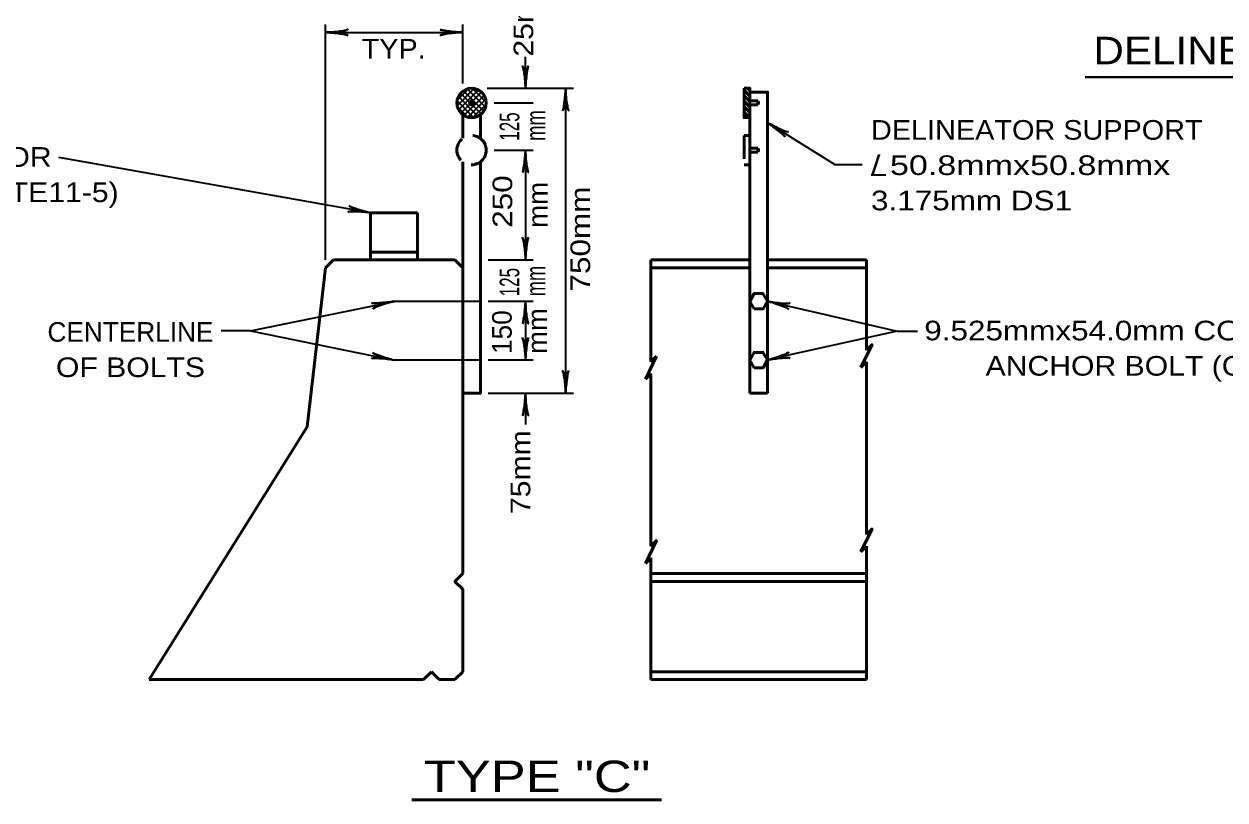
# Model space of a CAD drawing. Extents: x -105 to 751, y -65 to 479.
# Drawn here: x 308.2 to 492, y 149.8 to 268.5 of the extents above; entities that cross this region are included whole.
import ezdxf
from ezdxf.enums import TextEntityAlignment as Align

# ---------------------------------------------------------------- set-up
doc = ezdxf.new("R2010")
doc.units = 0
doc.header["$LTSCALE"] = 1.2
doc.linetypes.add('MEDIUM_DASHED', pattern=[4.5, 3, -1.5])
doc.layers.add('1', color=7, linetype='Continuous', lineweight=35)

msp = doc.modelspace()

# ---------------------------------------------------------------- hatches: boundary and pattern name
at = {"layer": '1'}
msp.add_hatch(color=256, dxfattribs=at).paths.add_polyline_path([(377.019, 256.406, 1), (376.419, 256.406, 1)])

# ---------------------------------------------------------------- linework, layer by layer
for p, q in [((354.369, 232.4), (354.369, 268.4)), ((375.369, 259.406), (375.369, 268.4)), ((354.369, 267.2), (375.369, 267.2)), ((384.969, 258.656), (384.969, 263.456)), ((374.513, 255.985), (377.138, 258.61)), ((374.514, 256.835), (376.293, 258.613)), ((377.688, 254.38), (374.695, 257.373)), ((374.733, 255.356), (377.767, 258.39)), ((378.2, 254.716), (375.031, 257.885)), ((375.088, 254.863), (378.261, 258.036)), ((378.597, 255.168), (375.484, 258.281)), ((375.558, 254.485), (378.64, 257.567)), ((378.869, 255.745), (376.06, 258.553)), ((378.962, 256.5), (376.814, 258.648)), ((379.119, 258.656), (392.319, 258.656)), ((391.119, 258.656), (391.119, 212)), ((377.037, 254.182), (374.498, 256.722)), ((376.131, 254.24), (374.553, 255.818)), ((376.155, 254.234), (378.892, 256.971)), ((376.938, 254.168), (378.953, 256.182)), ((380.169, 256.406), (386.169, 256.406)), ((380.169, 249.192), (386.169, 249.192)), ((384.969, 249.192), (384.969, 232.4)), ((361.269, 239.6), (313.525, 248.049)), ((437.882, 245.401), (440.147, 245.401)), ((379.269, 232.4), (386.169, 232.4)), ((342.873, 221.554), (364.869, 226.054)), ((378.069, 226.054), (364.869, 226.054)), ((386.169, 226.054), (379.269, 226.054)), ((384.969, 226.054), (384.969, 217.054)), ((342.873, 221.554), (338.372, 221.554)), ((342.873, 221.554), (364.869, 217.054)), ((441.854, 221.484), (444.959, 221.484)), ((378.069, 217.054), (364.869, 217.054)), ((386.169, 217.054), (379.269, 217.054)), ((379.269, 212), (392.319, 212)), ((384.969, 212), (384.969, 207.2))]:
    msp.add_line(p, q, dxfattribs=at)
at = {"layer": '1', "lineweight": 40}
msp.add_line((470.651, 260.331), (560.871, 260.331), dxfattribs=at)
at = {"layer": '1', "lineweight": 53}
for p, q in [((419.319, 257.466), (418.419, 258.366)), ((419.319, 256.618), (418.419, 257.518)), ((419.319, 258.315), (418.979, 258.656)), ((419.319, 255.769), (418.419, 256.669)), ((419.319, 254.921), (418.419, 255.821)), ((420.519, 256.706), (419.319, 256.706)), ((420.519, 256.106), (419.319, 256.106)), ((420.519, 256.706), (420.519, 256.106)), ((420.819, 256.406), (420.519, 256.406)), ((375.369, 250.993), (375.369, 254.593)), ((378.069, 250.992), (378.069, 254.592)), ((419.236, 254.156), (418.419, 254.972)), ((419.319, 254.156), (419.319, 212)), ((420.519, 249.492), (419.319, 249.492)), ((420.519, 248.892), (419.319, 248.892)), ((420.519, 249.492), (420.519, 248.892)), ((420.819, 249.192), (420.519, 249.192)), ((375.369, 247.392), (375.369, 184.4)), ((361.269, 239.6), (361.269, 232.4)), ((361.269, 239.6), (368.469, 239.6)), ((368.469, 239.6), (368.469, 232.4)), ((361.269, 233.6), (368.469, 233.6)), ((354.369, 231.2), (355.569, 232.4)), ((374.169, 232.4), (355.569, 232.4)), ((375.369, 231.2), (374.169, 232.4)), ((404.169, 216.8), (404.169, 232.4)), ((404.169, 232.4), (419.319, 232.4)), ((422.019, 232.4), (437.169, 232.4)), ((437.169, 218.6), (437.169, 232.4)), ((404.169, 231.2), (419.319, 231.2)), ((422.019, 231.2), (437.169, 231.2)), ((405.018, 217.649), (403.321, 214.152)), ((404.169, 216.8), (405.018, 217.649)), ((436.321, 215.952), (437.169, 216.8)), ((437.169, 216.8), (437.169, 190.4)), ((403.321, 214.152), (404.169, 215)), ((404.169, 215), (404.169, 188.6)), ((419.319, 212), (422.019, 212)), ((436.321, 187.752), (437.169, 188.6)), ((437.169, 188.6), (437.169, 168.2)), ((403.321, 185.952), (404.169, 186.8)), ((404.169, 186.8), (404.169, 168.2)), ((404.169, 184.4), (437.169, 184.4)), ((375.369, 182), (375.369, 169.4)), ((404.169, 183.2), (437.169, 183.2)), ((369.369, 168.2), (370.569, 169.4)), ((371.769, 168.2), (370.569, 169.4)), ((375.369, 169.4), (374.169, 168.2)), ((404.169, 169.4), (437.169, 169.4)), ((369.369, 168.2), (327.369, 168.2)), ((371.769, 168.2), (374.169, 168.2)), ((404.169, 168.2), (437.169, 168.2)), ((367.574, 149.773), (405.797, 149.773))]:
    msp.add_line(p, q, dxfattribs=at)
at = {"layer": '1', "linetype": 'MEDIUM_DASHED', "lineweight": 53}
for p, q in [((419.319, 251.442), (418.419, 251.442)), ((418.419, 251.442), (418.419, 246.942)), ((419.319, 246.942), (418.419, 246.942))]:
    msp.add_line(p, q, dxfattribs=at)
at = {"layer": '1', "lineweight": 53}
for points in [[(418.419, 258.656), (418.419, 254.156), (419.319, 254.156), (419.319, 258.656)], [(419.994, 224.892), (421.344, 224.908), (422.006, 226.085), (421.318, 227.246), (419.968, 227.231), (419.306, 226.054)], [(419.994, 215.892), (421.344, 215.908), (422.006, 217.085), (421.318, 218.246), (419.968, 218.231), (419.306, 217.054)]]:
    msp.add_lwpolyline(points, close=True, dxfattribs=at)
for points in [[(419.319, 258.056), (422.019, 258.056), (422.019, 212)], [(375.369, 212), (378.069, 212), (378.069, 247.393)], [(327.369, 168.2), (351.534, 206.871), (354.369, 231.2)], [(437.169, 218.6), (438.018, 219.449), (436.321, 215.952)], [(437.169, 190.4), (438.018, 191.249), (436.321, 187.752)], [(404.169, 188.6), (405.018, 189.449), (403.321, 185.952)], [(375.369, 182), (374.169, 183.2), (375.369, 184.4)]]:
    msp.add_lwpolyline(points, dxfattribs=at)
at = {"layer": '1'}
for points in [[(422.019, 253.397), (432.337, 246.996), (436.491, 246.996)], [(422.006, 226.085), (441.854, 221.484), (422.006, 217.085)]]:
    msp.add_lwpolyline(points, dxfattribs=at)
at = {"layer": '1', "lineweight": 53}
for radius in [2.25, 0.3]:
    msp.add_circle((376.719, 256.406), radius, dxfattribs=at)
at = {"layer": '1', "linetype": 'MEDIUM_DASHED', "lineweight": 53}
msp.add_circle((376.719, 249.192), 2.25, dxfattribs=at)
at = {"layer": '1', "lineweight": 40}
for centre, major_axis, ratio, start_param, end_param in [((355.714, 266.946), (-2.108, 0.211), 0.07063, 3.1407148, 5.41811), ((355.714, 266.946), (-2.108, 0.211), 0.07063, 3.1407148, 5.41811), ((355.679, 267.532), (-2.143, -0.187), 0.122415, 0.8963533, 3.1415927), ((355.679, 267.532), (-2.143, -0.187), 0.122415, 0.8963533, 3.1415927), ((374.06, 266.869), (2.143, 0.187), 0.122415, 0.8963533, 3.1415927), ((374.025, 267.454), (2.108, -0.211), 0.07063, 3.1407148, 5.41811), ((384.638, 259.965), (0.187, -2.143), 0.122415, 0.8963533, 3.1415927), ((384.638, 259.965), (0.187, -2.143), 0.122415, 0.8963533, 3.1415927), ((385.223, 260), (-0.211, -2.108), 0.07063, 3.1407148, 5.41811), ((385.223, 260), (-0.211, -2.108), 0.07063, 3.1407148, 5.41811), ((390.865, 257.311), (0.211, 2.108), 0.07063, 3.1407148, 5.41811), ((391.451, 257.346), (-0.187, 2.143), 0.122415, 0.8963533, 3.1415927), ((423.028, 252.472), (-1.68, 1.29), 0.07063, 3.1407148, 5.41811), ((423.028, 252.472), (-1.68, 1.29), 0.07063, 3.1407148, 5.41811), ((423.307, 252.988), (-1.92, 0.97), 0.122415, 0.8963533, 3.1415927), ((423.307, 252.988), (-1.92, 0.97), 0.122415, 0.8963533, 3.1415927), ((384.715, 247.848), (0.211, 2.108), 0.07063, 3.1407148, 5.41811), ((384.715, 247.848), (0.211, 2.108), 0.07063, 3.1407148, 5.41811), ((385.301, 247.883), (-0.187, 2.143), 0.122415, 0.8963533, 3.1415927), ((385.301, 247.883), (-0.187, 2.143), 0.122415, 0.8963533, 3.1415927), ((359.922, 239.502), (2.143, -0.189), 0.122415, 0.8963533, 3.1415927), ((359.99, 240.084), (2.039, -0.575), 0.07063, 3.1407148, 5.41811), ((384.638, 233.71), (0.187, -2.143), 0.122415, 0.8963533, 3.1415927), ((384.638, 233.71), (0.187, -2.143), 0.122415, 0.8963533, 3.1415927), ((385.223, 233.745), (-0.211, -2.108), 0.07063, 3.1407148, 5.41811), ((385.223, 233.745), (-0.211, -2.108), 0.07063, 3.1407148, 5.41811), ((363.501, 226.033), (-2.107, -0.216), 0.07063, 6.2823074, 8.5597026), ((363.501, 226.033), (-2.107, -0.216), 0.07063, 6.2823074, 8.5597026), ((363.653, 225.467), (2.062, 0.613), 0.122415, 0.8963533, 3.1415927), ((363.653, 225.467), (2.062, 0.613), 0.122415, 0.8963533, 3.1415927), ((384.715, 224.709), (0.211, 2.108), 0.07063, 3.1407148, 5.41811), ((384.715, 224.709), (0.211, 2.108), 0.07063, 3.1407148, 5.41811), ((385.301, 224.744), (-0.187, 2.143), 0.122415, 0.8963533, 3.1415927), ((385.301, 224.744), (-0.187, 2.143), 0.122415, 0.8963533, 3.1415927), ((423.258, 225.534), (2.006, -0.681), 0.07063, 6.2823074, 8.5597026), ((423.258, 225.534), (2.006, -0.681), 0.07063, 6.2823074, 8.5597026), ((423.356, 226.112), (-2.13, 0.301), 0.122415, 0.8963533, 3.1415927), ((423.356, 226.112), (-2.13, 0.301), 0.122415, 0.8963533, 3.1415927), ((384.638, 218.363), (0.187, -2.143), 0.122415, 0.8963533, 3.1415927), ((384.638, 218.363), (0.187, -2.143), 0.122415, 0.8963533, 3.1415927), ((385.223, 218.398), (-0.211, -2.108), 0.07063, 3.1407148, 5.41811), ((385.223, 218.398), (-0.211, -2.108), 0.07063, 3.1407148, 5.41811), ((363.52, 216.991), (2.137, -0.246), 0.122415, 0.8963533, 3.1415927), ((363.603, 217.572), (2.023, -0.629), 0.07063, 3.1407148, 5.41811), ((423.213, 217.692), (-2.052, -0.647), 0.122415, 0.8963533, 3.1415927), ((423.374, 217.128), (2.103, 0.25), 0.07063, 6.2823074, 8.5597026), ((390.788, 213.31), (0.187, -2.143), 0.122415, 0.8963533, 3.1415927), ((390.788, 213.31), (0.187, -2.143), 0.122415, 0.8963533, 3.1415927), ((391.373, 213.345), (-0.211, -2.108), 0.07063, 3.1407148, 5.41811), ((391.373, 213.345), (-0.211, -2.108), 0.07063, 3.1407148, 5.41811), ((384.715, 210.655), (0.211, 2.108), 0.07063, 3.1407148, 5.41811), ((385.301, 210.691), (-0.187, 2.143), 0.122415, 0.8963533, 3.1415927)]:
    msp.add_ellipse(centre, major_axis=major_axis, ratio=ratio, start_param=start_param, end_param=end_param, dxfattribs=at)

# ---------------------------------------------------------------- texts
at = {"layer": '1'}
for s, width, p in [('25mm', 1.15, (386.155, 263.487)), ('125', 0.65, (384.023, 250.615)), ('mm', 0.7, (388.023, 250.615)), ('250', 1.2, (382.942, 237.303)), ('mm', 1.05, (388.342, 237.303)), ('750mm', 1.2, (394.859, 227.557)), ('125', 0.65, (384.023, 226.817)), ('mm', 0.7, (388.023, 226.817)), ('mm', 1.05, (388.261, 217.998)), ('75mm', 1.15, (385.707, 193.509))]:
    msp.add_text(s, height=3, rotation=90, dxfattribs=dict(at, width=width)).set_placement(p)
for s, height, width, p in [('DELINEATOR SUPPORT DS2', 4.2, 1.15, (471.899, 262.327)), ('DELINEATOR SUPPORT', 3, 1.1, (437.858, 250.782)), ('TYPE B-1 DELINEATOR', 3, 1.15, (261.174, 246.643)), ('/ 50.8mmx50.8mmx', 3, 1.3, (437.858, 245.382)), ('(FOR DETAILS, SEE TE11-5)', 3, 1.15, (261.174, 241.243)), ('3.175mm DS1', 3, 1.2, (437.858, 239.982)), ('TYPE "C"', 4.8, 1.25, (369.403, 150.993))]:
    msp.add_text(s, height=height, dxfattribs=dict(at, width=width)).set_placement(p)
for s, width, p in [('TYP.', 1.1, (364.798, 263.2)), ('9.525mmx54.0mm CONCRETE EXPANSION STUD', 1.2, (502.049, 220.089)), ('OF BOLTS', 1.15, (324.51, 214.475)), ('ANCHOR BOLT (CORROSION RESISTANT)', 1.15, (502.049, 214.689))]:
    msp.add_text(s, height=3, dxfattribs=dict(at, width=width)).set_placement(p, align=Align.CENTER)
msp.add_text('150', height=3, rotation=90, dxfattribs=at).set_placement((382.861, 217.998))
msp.add_text('CENTERLINE', height=3, dxfattribs=at).set_placement((324.51, 219.875), align=Align.CENTER)

doc.saveas('drawing.dxf')
